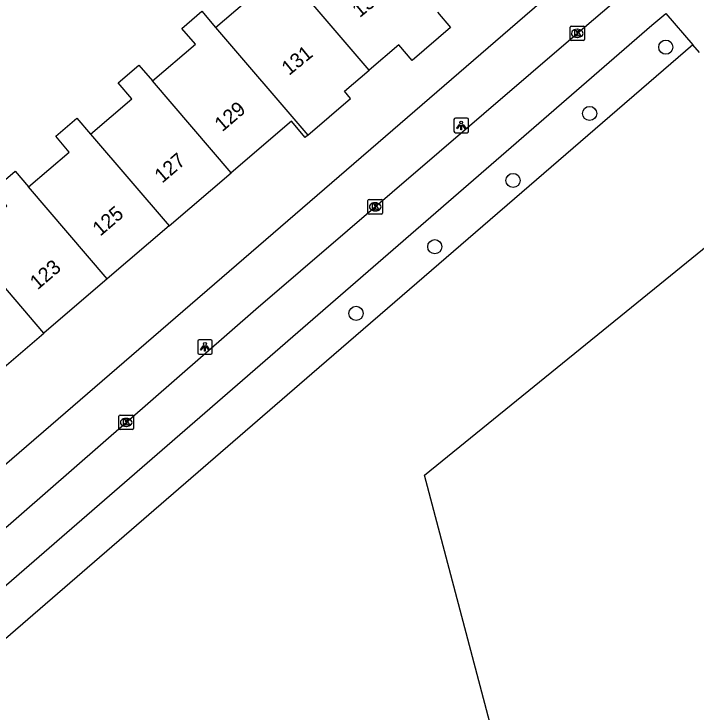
# Model space of a CAD drawing. Extents: x 158474 to 159560, y 388525 to 389605.
# Drawn here: x 159135.46 to 159182.53, y 389030.91 to 389079.07 of the extents above; entities that cross this region are included whole.
import ezdxf

# ---------------------------------------------------------------- set-up
doc = ezdxf.new("R2010")
doc.units = 0
for name, color, linetype in [('IMGEO_Boom', 7, 'Continuous'), ('IMGEO_Fietspad_gesloten', 7, 'Continuous'), ('IMGEO_Groenvoorziening', 7, 'Continuous'), ('IMGEO_Kolk', 7, 'Continuous'), ('IMGEO_Lichtpunt', 7, 'Continuous'), ('IMGEO_Pand', 7, 'Continuous'), ('IMGEO_Pand_nummerreeks', 7, 'Continuous'), ('IMGEO_Voetpad_open', 7, 'Continuous')]:
    doc.layers.add(name, color=color, linetype=linetype)

msp = doc.modelspace()

# ---------------------------------------------------------------- linework, layer by layer
at = {"layer": 'IMGEO_Boom'}
for centre in [(159180.439, 389076.775), (159175.181, 389072.202), (159169.898, 389067.579), (159164.5, 389063.006), (159159.064, 389058.408)]:
    msp.add_circle(centre, 0.489, dxfattribs=at)
at = {"layer": 'IMGEO_Fietspad_gesloten'}
for points in [[(159121.218, 389031.725), (159121.614, 389032.055), (159152.159, 389058.692), (159174.203, 389077.614), (159178.548, 389081.349), (159179.526, 389082.19)], [(159123.845, 389030.074), (159179.477, 389078.282), (159180.43, 389079.087)]]:
    msp.add_lwpolyline(points, dxfattribs=at)
at = {"layer": 'IMGEO_Groenvoorziening'}
for points in [[(159182.297, 389076.941), (159156.026, 389054.244), (159128.905, 389030.814), (159125.639, 389027.992)], [(159172.865, 389012.863), (159163.799, 389047.245), (159177.696, 389058.53), (159196.313, 389073.65), (159210.179, 389059.558), (159212.821, 389051.632), (159214.2, 389042.452), (159218.174, 389020.125)]]:
    msp.add_lwpolyline(points, dxfattribs=at)
at = {"layer": 'IMGEO_Kolk'}
for p, q in [((159173.831, 389077.3), (159173.831, 389078.152)), ((159173.906, 389078.226), (159174.758, 389078.226)), ((159174.832, 389078.152), (159174.832, 389077.3)), ((159174.319, 389078.006), (159174.344, 389078.006)), ((159174.758, 389077.226), (159173.906, 389077.226)), ((159174.342, 389077.446), (159174.317, 389077.446)), ((159159.889, 389065.333), (159159.889, 389066.185)), ((159159.964, 389066.259), (159160.816, 389066.259)), ((159160.89, 389066.185), (159160.89, 389065.333)), ((159160.377, 389066.039), (159160.402, 389066.039)), ((159160.816, 389065.259), (159159.964, 389065.259)), ((159160.4, 389065.479), (159160.375, 389065.479)), ((159142.709, 389050.462), (159142.709, 389051.314)), ((159142.784, 389051.388), (159143.636, 389051.388)), ((159143.197, 389051.168), (159143.222, 389051.168)), ((159143.71, 389051.314), (159143.71, 389050.462)), ((159143.636, 389050.388), (159142.784, 389050.388)), ((159143.22, 389050.608), (159143.195, 389050.608))]:
    msp.add_line(p, q, dxfattribs=at)
for points in [[(159173.831, 389077.3), (159173.831, 389078.152)], [(159173.906, 389078.226), (159174.758, 389078.226)], [(159174.832, 389078.152), (159174.832, 389077.3)], [(159174.152, 389077.926), (159174.275, 389077.926), (159174.275, 389077.775), (159174.405, 389077.926), (159174.569, 389077.926), (159174.423, 389077.775), (159174.576, 389077.526), (159174.424, 389077.526), (159174.339, 389077.69), (159174.275, 389077.623), (159174.275, 389077.526), (159174.152, 389077.526), (159174.152, 389077.926)], [(159174.758, 389077.226), (159173.906, 389077.226)], [(159159.889, 389065.333), (159159.889, 389066.185)], [(159159.964, 389066.259), (159160.816, 389066.259)], [(159160.89, 389066.185), (159160.89, 389065.333)], [(159160.21, 389065.959), (159160.333, 389065.959), (159160.333, 389065.808), (159160.463, 389065.959), (159160.627, 389065.959), (159160.481, 389065.808), (159160.634, 389065.559), (159160.482, 389065.559), (159160.397, 389065.723), (159160.333, 389065.656), (159160.333, 389065.559), (159160.21, 389065.559), (159160.21, 389065.959)], [(159160.816, 389065.259), (159159.964, 389065.259)], [(159142.709, 389050.462), (159142.709, 389051.314)], [(159142.784, 389051.388), (159143.636, 389051.388)], [(159143.71, 389051.314), (159143.71, 389050.462)], [(159143.03, 389051.088), (159143.153, 389051.088), (159143.153, 389050.937), (159143.283, 389051.088), (159143.447, 389051.088), (159143.301, 389050.937), (159143.454, 389050.688), (159143.302, 389050.688), (159143.217, 389050.852), (159143.153, 389050.785), (159143.153, 389050.688), (159143.03, 389050.688), (159143.03, 389051.088)], [(159143.636, 389050.388), (159142.784, 389050.388)]]:
    msp.add_lwpolyline(points, dxfattribs=at)
for centre, start, end in [((159173.908, 389078.15), 91.552, 178.448), ((159173.908, 389078.15), 91.552, 178.448), ((159174.756, 389078.15), 1.552, 88.448), ((159174.756, 389078.15), 1.552, 88.448), ((159173.908, 389077.302), 181.552, 268.448), ((159173.908, 389077.302), 181.552, 268.448), ((159174.756, 389077.302), 271.552, 358.448), ((159174.756, 389077.302), 271.552, 358.448), ((159159.966, 389066.183), 91.552, 178.448), ((159159.966, 389066.183), 91.552, 178.448), ((159160.814, 389066.183), 1.552, 88.448), ((159160.814, 389066.183), 1.552, 88.448), ((159159.966, 389065.335), 181.552, 268.448), ((159159.966, 389065.335), 181.552, 268.448), ((159160.814, 389065.335), 271.552, 358.448), ((159160.814, 389065.335), 271.552, 358.448), ((159142.786, 389051.312), 91.552, 178.448), ((159142.786, 389051.312), 91.552, 178.448), ((159143.634, 389051.312), 1.552, 88.448), ((159143.634, 389051.312), 1.552, 88.448), ((159142.786, 389050.464), 181.552, 268.448), ((159142.786, 389050.464), 181.552, 268.448), ((159143.634, 389050.464), 271.552, 358.448), ((159143.634, 389050.464), 271.552, 358.448)]:
    msp.add_arc(centre, 0.0765, start, end, dxfattribs=at)
for centre, major_axis, ratio, start_param, end_param in [((159174.318, 389077.726), (-0.387, 0.002), 0.722429, 4.712389, 7.853982), ((159174.343, 389077.726), (-0.39, 0.002), 0.717154, 1.570796, 4.712389), ((159160.376, 389065.759), (-0.387, 0.002), 0.722429, 4.712389, 7.853982), ((159160.401, 389065.759), (-0.39, 0.002), 0.717154, 1.570796, 4.712389), ((159143.196, 389050.888), (-0.387, 0.002), 0.722429, 4.712389, 7.853982), ((159143.221, 389050.888), (-0.39, 0.002), 0.717154, 1.570796, 4.712389)]:
    msp.add_ellipse(centre, major_axis=major_axis, ratio=ratio, start_param=start_param, end_param=end_param, dxfattribs=at)
at = {"layer": 'IMGEO_Lichtpunt'}
for p, q in [((159166.726, 389071.871), (159165.918, 389071.871)), ((159166.726, 389071.871), (159165.918, 389071.871)), ((159165.824, 389071.776), (159165.824, 389070.969)), ((159165.824, 389071.776), (159165.824, 389070.969)), ((159166.82, 389070.969), (159166.82, 389071.776)), ((159166.82, 389070.969), (159166.82, 389071.776)), ((159165.918, 389070.875), (159166.726, 389070.875)), ((159165.918, 389070.875), (159166.726, 389070.875)), ((159148.14, 389056.499), (159148.14, 389055.692)), ((159148.14, 389056.499), (159148.14, 389055.692)), ((159149.042, 389056.594), (159148.234, 389056.594)), ((159149.042, 389056.594), (159148.234, 389056.594)), ((159149.136, 389055.692), (159149.136, 389056.499)), ((159149.136, 389055.692), (159149.136, 389056.499)), ((159148.234, 389055.598), (159149.042, 389055.598)), ((159148.234, 389055.598), (159149.042, 389055.598))]:
    msp.add_line(p, q, dxfattribs=at)
for points in [[(159166.198, 389071.44), (159166.237, 389071.412), (159166.049, 389071.15), (159166.011, 389071.177), (159166.198, 389071.44)], [(159166.3, 389071.392), (159166.347, 389071.392), (159166.347, 389071.07), (159166.3, 389071.07), (159166.3, 389071.392)], [(159166.41, 389071.412), (159166.448, 389071.439), (159166.635, 389071.177), (159166.596, 389071.149), (159166.41, 389071.412)], [(159148.514, 389056.163), (159148.553, 389056.135), (159148.365, 389055.873), (159148.327, 389055.9), (159148.514, 389056.163)], [(159148.616, 389056.115), (159148.663, 389056.115), (159148.663, 389055.793), (159148.616, 389055.793), (159148.616, 389056.115)], [(159148.726, 389056.135), (159148.764, 389056.162), (159148.951, 389055.9), (159148.912, 389055.872), (159148.726, 389056.135)]]:
    msp.add_lwpolyline(points, dxfattribs=at)
for centre in [(159166.323, 389071.574), (159148.639, 389056.297)]:
    msp.add_circle(centre, 0.0994, dxfattribs=at)
for centre, start, end in [((159165.918, 389071.776), 90, 180), ((159165.918, 389071.776), 90, 180), ((159166.726, 389071.776), 0, 90), ((159166.726, 389071.776), 0, 90), ((159165.918, 389070.969), 180, 270), ((159165.918, 389070.969), 180, 270), ((159166.726, 389070.969), 270, 0), ((159166.726, 389070.969), 270, 360), ((159148.234, 389056.499), 90, 180), ((159148.234, 389056.499), 90, 180), ((159149.042, 389056.499), 0, 90), ((159149.042, 389056.499), 0, 90), ((159148.234, 389055.692), 180, 270), ((159148.234, 389055.692), 180, 270), ((159149.042, 389055.692), 270, 0), ((159149.042, 389055.692), 270, 360)]:
    msp.add_arc(centre, 0.0946, start, end, dxfattribs=at)
at = {"layer": 'IMGEO_Pand'}
for points in [[(159149.379, 389078.139), (159154.041, 389082.129)], [(159159.972, 389075.198), (159154.041, 389082.129)], [(159145.021, 389074.446), (159147.977, 389076.976), (159147.044, 389078.065), (159148.429, 389079.25), (159149.379, 389078.139)], [(159164.675, 389079.192), (159165.593, 389078.12), (159162.943, 389075.852), (159162.01, 389076.942), (159159.972, 389075.198)], [(159149.379, 389078.139), (159155.739, 389070.705)], [(159140.748, 389070.777), (159143.604, 389073.221), (159142.662, 389074.322), (159144.085, 389075.541), (159145.021, 389074.446)], [(159155.739, 389070.705), (159158.69, 389073.231), (159158.26, 389073.733), (159159.972, 389075.198)], [(159150.446, 389068.106), (159145.021, 389074.446)], [(159136.466, 389067.13), (159139.282, 389069.541), (159138.353, 389070.626), (159139.81, 389071.874), (159140.748, 389070.777)], [(159155.739, 389070.705), (159155.562, 389070.553), (159154.608, 389071.668), (159150.446, 389068.106)], [(159140.748, 389070.777), (159146.167, 389064.444)], [(159132.093, 389063.383), (159134.961, 389065.837), (159134.032, 389066.923), (159135.539, 389068.213), (159136.466, 389067.13)], [(159146.167, 389064.444), (159150.446, 389068.106)], [(159141.894, 389060.786), (159136.466, 389067.13)], [(159146.167, 389064.444), (159141.894, 389060.786)], [(159137.519, 389057.042), (159132.093, 389063.383)], [(159141.894, 389060.786), (159137.519, 389057.042)], [(159133.159, 389053.31), (159137.519, 389057.042)]]:
    msp.add_lwpolyline(points, dxfattribs=at)
at = {"layer": 'IMGEO_Voetpad_open'}
for points in [[(159177.566, 389084.843), (159176.445, 389083.875), (159120.451, 389035.544)], [(159180.43, 389079.087), (159182.297, 389076.941)], [(159182.754, 389076.416), (159182.297, 389076.941)]]:
    msp.add_lwpolyline(points, dxfattribs=at)

# ---------------------------------------------------------------- texts
at = {"layer": 'IMGEO_Pand_nummerreeks'}
for s, rotation, p in [('133', 39.2871, (159159.317, 389078.772)), ('131', 39.2871, (159154.44, 389074.781)), ('129', 40.5595, (159149.837, 389070.901)), ('127', 40.5595, (159145.691, 389067.353)), ('125', 40.5595, (159141.415, 389063.693)), ('123', 40.5595, (159137.093, 389059.994))]:
    msp.add_text(s, height=1, rotation=rotation, dxfattribs=at).set_placement(p)

doc.saveas('drawing.dxf')
